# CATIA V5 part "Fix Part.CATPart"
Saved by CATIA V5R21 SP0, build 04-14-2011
Part number: Part4
Bounding box of the stored display mesh (mm): x -100 to 100, y -30 to 50, z -10 to 111
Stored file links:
  E:\cadcim\Projects\CATIA V5-6R2015_Menuscript\WebResources\CATIA V5-6r2015_partfiles\Partfiles\c16_catia_v5_6r2015_prt\Rack Joint-(Fig16-57)\Fix Part.CATPart
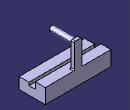
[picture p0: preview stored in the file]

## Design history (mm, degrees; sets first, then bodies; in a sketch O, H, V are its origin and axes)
Body1 (main body)
  Sketch1 on yz-plane, origin (0, 0, 0), H (0, 1, 0), V (0, 0, 1)
    line L1 (50, 35) -> (50, -10)
    line L2 (50, -10) -> (-30, -10)
    line L3 (0, 15) -> (20, 15)
    line L4 (20, 15) -> (20, 35)
    point P5 (0, 15)
    reference intersected line E1 through (0, 0) direction (-1, 0) from xy-plane
    reference intersected line E3 through (0, 0) direction (0, 1) from zx-plane
    line L5 (20, 35) -> (50, 35)
    reference intersected line E4 through (0, 0) direction (-1, 0) from xy-plane
    reference intersected line E6 through (0, 0) direction (0, 1) from zx-plane
    line L6 (0, 15) -> (0, 24)
    line L7 (0, 24) -> (-30, 24)
    line L8 (-30, 24) -> (-30, -10)
    distance H L2 = 10
    distance V L1 = 50
    distance E1 L3 = 15
    length L6 = 9
    length L4 = 20
    length L3 = 20
    length L2 = 80
    vertical: L1 V, L4 V, E3 V, E6 V, L6 V, L8 V
    horizontal: L2 H, L3 H, E1 H, L5 H, E4 H, L7 H
    perpendicularity: E1 L1
    coincidence: P5 V
  Pad1: profile Sketch1, direction (1, 0, 0), length 100, mirrored extent
  Sketch2 on face of Pad1 from Sketch1.L1, origin (0, 50, 0), H (-1, 0, 0), V (0, 0, 1)
    circle A1 centre (0, 100) radius 7.5
    point P1 (0, 100)
    radius A1 = 7.5
    distance H P1 = 100
    coincidence: P1 V
  Pad2: profile Sketch2, direction (0, -1, 0), up to face of Pad1 from Sketch1.L8
  Sketch3 on face of Pad1 from Sketch1.L1, origin (0, 50, 0), H (-1, 0, 0), V (0, 0, 1)
    line L1 (-11, 111) -> (11, 111)
    line L2 (11, 111) -> (11, -10)
    line L3 (11, -10) -> (-11, -10)
    line L4 (-11, -10) -> (-11, 111)
    length L3 = 22
    distance V L2 = 11
    distance L1 L3 = 121
    distance L3 H = 10
    horizontal: L1 H, L3 H
    vertical: L2 V, L4 V
  Pad3: profile Sketch3, direction (0, -1, 0), length 10
  Fillet1: radius 3, on edge [end face of Pad3 | face of Pad1 from Sketch1.L5]; edge [face of Pad3 from Sketch3.L4 | face of Pad1 from Sketch1.L5]; edge [face of Pad1 from Sketch1.L5 | face of Pad3 from Sketch3.L2]; edge [face of Pad2 from Sketch2.A1 | end face of Pad3]; edge [face of Pad3 from Sketch3.L1 | face of Pad3 from Sketch3.L4]; edge [face of Pad3 from Sketch3.L2 | face of Pad3 from Sketch3.L1]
